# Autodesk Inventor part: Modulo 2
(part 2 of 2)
feature "Pattern of M2.15:24"
feature "Pattern of M2.15:25"
feature "Pattern of M2.15:26"
feature "Pattern of M2.15:27"
feature "Pattern of M2.15:28"
feature "Pattern of M2.15:29"
feature "Pattern of M2.15:30"
feature "Pattern of M2.15:31"
feature "Pattern of M2.15:32"
feature "Pattern of M2.15:33"
feature "Pattern of M2.15:34"
feature "Pattern of M2.15:35"
feature "Pattern of M2.15:36"
feature "Pattern of M2.15:37"
feature "Pattern of M2.15:38"
feature "Pattern of M2.15:39"
feature "Pattern of M2.15:40"
feature "Pattern of M2.15:41"
feature "Pattern of M2.15:42"
feature "Pattern of M2.15:43"
feature "Pattern of M2.15:44"
feature "Pattern of M2.15:45"
feature "Pattern of M2.15:46"
feature "Pattern of M2.15:47"
feature "Pattern of M2.15:48"
feature "Pattern of M2.15:49"
feature "Pattern of M2.15:50"
feature "Pattern of M2.15:51"
feature "Pattern of M2.15:52"
feature "Pattern of M2.15:53"
feature "Pattern of M2.15:54"
feature "Pattern of M2.15:55"
feature "Pattern of M2.15:56"
feature "Pattern of M2.15:57"
feature "Pattern of M2.15:58"
feature "Pattern of M2.15:59"
feature "Pattern of M2.15:60"
feature "Pattern of M2.15:61"
feature "Pattern of M2.15:62"
feature "Pattern of M2.15:63"
feature "Pattern of M2.15:64"
feature "Pattern of M2.15:65"
feature "Pattern of M2.15:66"
feature "Pattern of M2.15:67"
feature "Pattern of M2.15:68"
feature "Pattern of M2.15:69"
feature "Pattern of M2.15:70"
feature "Pattern of M2.15:71"
feature "Pattern of M2.15:72"
feature "Pattern of M2.15:73"
feature "Pattern of M2.44:74"
feature "Pattern of M2.44:75"
feature "Pattern of M2.44:76"
feature "Pattern of M2.44:77"
feature "Pattern of M2.44:78"
feature "Pattern of M2.44:79"
feature "Pattern of M2.44:80"
feature "Pattern of M2.44:81"
feature "Pattern of M2.44:82"
feature "Pattern of M2.44:83"
feature "Pattern of M2.44:84"
feature "Pattern of M2.44:85"
feature "Pattern of M2.44:86"
feature "Pattern of M2.44:87"
feature "Pattern of M2.44:88"
feature "Pattern of M2.44:89"
feature "Pattern of M2.44:90"
feature "Pattern of M2.44:91"
feature "Pattern of M2.44:92"
feature "Pattern of M2.44:93"
feature "Pattern of M2.44:94"
feature "Pattern of M2.44:95"
feature "Pattern of M2.44:96"
feature "Pattern of M2.44:97"
feature "Pattern of M2.44:98"
feature "Pattern of M2.44:99"
feature "Pattern of M2.44:100"
feature "Pattern of M2.44:101"
feature "Pattern of M2.44:102"
feature "Pattern of M2.44:103"
node "Cimento"
move_body "Move1" dims "d414" = -10
move_body "Move2" dims "d417" = -10
other parameters: "T_P_L" = 115 [user parameter; used in 102 equation terms], "T_P_P" = 58 [user parameter; used in 15 equation terms], "A_P_L" = 115 [user parameter], "A_P_P" = 58 [user parameter], "d267" = 15, "d412" = 0, "d413" = 0, "d415" = 0, "d416" = 0
